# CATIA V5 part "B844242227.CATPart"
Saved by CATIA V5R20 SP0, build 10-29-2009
Part number: B844242227
Revision: 2
Definition: design
Nomenclature: B844242227
Source: made
Description: NOT SPECIFIED
Bounding box of the stored display mesh (mm): x -20.5 to 20.5, y -20.5 to 20.5, z -22 to 27
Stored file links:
  C:\Users\Utente\Desktop\3D files B844\B844242227.CATPart
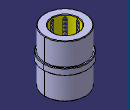
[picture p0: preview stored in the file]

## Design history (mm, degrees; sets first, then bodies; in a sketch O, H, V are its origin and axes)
Body1 "MANIFOLD_SOLID_BREP #38" (main body)
  Solid1: solid without history
Body2 "MANIFOLD_SOLID_BREP #76"
  Solid2: solid without history
Body3 "MANIFOLD_SOLID_BREP #114"
  Solid3: solid without history
Body4 "MANIFOLD_SOLID_BREP #152"
  Solid4: solid without history
Body5 "MANIFOLD_SOLID_BREP #190"
  Solid5: solid without history
Body6 "MANIFOLD_SOLID_BREP #228"
  Solid6: solid without history
Body7 "MANIFOLD_SOLID_BREP #266"
  Solid7: solid without history
Body8 "MANIFOLD_SOLID_BREP #304"
  Solid8: solid without history
Body9 "MANIFOLD_SOLID_BREP #2370"
  Solid9: solid without history
Body10 "MANIFOLD_SOLID_BREP #2408"
  Solid10: solid without history
Body11 "MANIFOLD_SOLID_BREP #2446"
  Solid11: solid without history
Body12 "MANIFOLD_SOLID_BREP #2484"
  Solid12: solid without history
Body13 "MANIFOLD_SOLID_BREP #2522"
  Solid13: solid without history
Body14 "MANIFOLD_SOLID_BREP #2560"
  Solid14: solid without history
Body15 "MANIFOLD_SOLID_BREP #2598"
  Solid15: solid without history
Body16 "MANIFOLD_SOLID_BREP #2636"
  Solid16: solid without history
Body17 "MANIFOLD_SOLID_BREP #2674"
  Solid17: solid without history
Body18 "MANIFOLD_SOLID_BREP #2712"
  Solid18: solid without history
Body19 "MANIFOLD_SOLID_BREP #2750"
  Solid19: solid without history
Body20 "MANIFOLD_SOLID_BREP #2788"
  Solid20: solid without history
Body21 "MANIFOLD_SOLID_BREP #2826"
  Solid21: solid without history
Body22 "MANIFOLD_SOLID_BREP #2864"
  Solid22: solid without history
Body23 "MANIFOLD_SOLID_BREP #2902"
  Solid23: solid without history
Body24 "MANIFOLD_SOLID_BREP #2940"
  Solid24: solid without history
Body25 "MANIFOLD_SOLID_BREP #2978"
  Solid25: solid without history
Body26 "MANIFOLD_SOLID_BREP #3016"
  Solid26: solid without history
Body27 "MANIFOLD_SOLID_BREP #3054"
  Solid27: solid without history
Body28 "MANIFOLD_SOLID_BREP #3092"
  Solid28: solid without history
Body29 "MANIFOLD_SOLID_BREP #3130"
  Solid29: solid without history
Body30 "MANIFOLD_SOLID_BREP #3168"
  Solid30: solid without history
Body31 "MANIFOLD_SOLID_BREP #3206"
  Solid31: solid without history
Body32 "MANIFOLD_SOLID_BREP #3244"
  Solid32: solid without history
Body33 "MANIFOLD_SOLID_BREP #3282"
  Solid33: solid without history
Body34 "MANIFOLD_SOLID_BREP #3320"
  Solid34: solid without history
Body35 "MANIFOLD_SOLID_BREP #3358"
  Solid35: solid without history
Body36 "MANIFOLD_SOLID_BREP #3396"
  Solid36: solid without history
Body37 "MANIFOLD_SOLID_BREP #3434"
  Solid37: solid without history
Body38 "MANIFOLD_SOLID_BREP #3472"
  Solid38: solid without history
Body39 "MANIFOLD_SOLID_BREP #3510"
  Solid39: solid without history
Body40 "MANIFOLD_SOLID_BREP #3548"
  Solid40: solid without history
Body41 "MANIFOLD_SOLID_BREP #3586"
  Solid41: solid without history
Body42 "MANIFOLD_SOLID_BREP #3624"
  Solid42: solid without history
Body43 "MANIFOLD_SOLID_BREP #3662"
  Solid43: solid without history
Body44 "MANIFOLD_SOLID_BREP #3700"
  Solid44: solid without history
Body45 "MANIFOLD_SOLID_BREP #3738"
  Solid45: solid without history
Body46 "MANIFOLD_SOLID_BREP #3776"
  Solid46: solid without history
Body47 "MANIFOLD_SOLID_BREP #3814"
  Solid47: solid without history
Body48 "MANIFOLD_SOLID_BREP #3852"
  Solid48: solid without history
Body49 "MANIFOLD_SOLID_BREP #3890"
  Solid49: solid without history
Body50 "MANIFOLD_SOLID_BREP #3928"
  Solid50: solid without history
Body51 "MANIFOLD_SOLID_BREP #3966"
  Solid51: solid without history
Body52 "MANIFOLD_SOLID_BREP #4004"
  Solid52: solid without history
Body53 "MANIFOLD_SOLID_BREP #4042"
  Solid53: solid without history
Body54 "MANIFOLD_SOLID_BREP #4080"
  Solid54: solid without history
Body55 "MANIFOLD_SOLID_BREP #4118"
  Solid55: solid without history
Body56 "MANIFOLD_SOLID_BREP #4156"
  Solid56: solid without history
Body57 "MANIFOLD_SOLID_BREP #4194"
  Solid57: solid without history
Body58 "MANIFOLD_SOLID_BREP #4232"
  Solid58: solid without history
Body59 "MANIFOLD_SOLID_BREP #4270"
  Solid59: solid without history
Body60 "MANIFOLD_SOLID_BREP #4308"
  Solid60: solid without history
Body61 "MANIFOLD_SOLID_BREP #4346"
  Solid61: solid without history
Body62 "MANIFOLD_SOLID_BREP #4384"
  Solid62: solid without history
Body63 "MANIFOLD_SOLID_BREP #4422"
  Solid63: solid without history
Body64 "MANIFOLD_SOLID_BREP #4460"
  Solid64: solid without history
Body65 "MANIFOLD_SOLID_BREP #4498"
  Solid65: solid without history
Body66 "MANIFOLD_SOLID_BREP #4536"
  Solid66: solid without history
Body67 "MANIFOLD_SOLID_BREP #4574"
  Solid67: solid without history
Body68 "MANIFOLD_SOLID_BREP #4612"
  Solid68: solid without history
Body69 "MANIFOLD_SOLID_BREP #4650"
  Solid69: solid without history
Body70 "MANIFOLD_SOLID_BREP #4688"
  Solid70: solid without history
Body71 "MANIFOLD_SOLID_BREP #4726"
  Solid71: solid without history
Body72 "MANIFOLD_SOLID_BREP #4764"
  Solid72: solid without history
Body73 "MANIFOLD_SOLID_BREP #4802"
  Solid73: solid without history
Body74 "MANIFOLD_SOLID_BREP #4840"
  Solid74: solid without history
Body75 "MANIFOLD_SOLID_BREP #4878"
  Solid75: solid without history
Body76 "MANIFOLD_SOLID_BREP #4916"
  Solid76: solid without history
Body77 "MANIFOLD_SOLID_BREP #4954"
  Solid77: solid without history
Body78 "MANIFOLD_SOLID_BREP #4992"
  Solid78: solid without history
Body79 "MANIFOLD_SOLID_BREP #5030"
  Solid79: solid without history
Body80 "MANIFOLD_SOLID_BREP #5068"
  Solid80: solid without history
Body81 "MANIFOLD_SOLID_BREP #5106"
  Solid81: solid without history
Body82 "MANIFOLD_SOLID_BREP #5144"
  Solid82: solid without history
Body83 "MANIFOLD_SOLID_BREP #5182"
  Solid83: solid without history
Body84 "MANIFOLD_SOLID_BREP #5220"
  Solid84: solid without history
Body85 "MANIFOLD_SOLID_BREP #5258"
  Solid85: solid without history
Body86 "MANIFOLD_SOLID_BREP #5296"
  Solid86: solid without history
Body87 "MANIFOLD_SOLID_BREP #5334"
  Solid87: solid without history
Body88 "MANIFOLD_SOLID_BREP #5372"
  Solid88: solid without history
Body89 "MANIFOLD_SOLID_BREP #5410"
  Solid89: solid without history
Body90 "MANIFOLD_SOLID_BREP #5448"
  Solid90: solid without history
Body91 "MANIFOLD_SOLID_BREP #5486"
  Solid91: solid without history
Body92 "MANIFOLD_SOLID_BREP #5524"
  Solid92: solid without history
Body93 "MANIFOLD_SOLID_BREP #5562"
  Solid93: solid without history
Body94 "MANIFOLD_SOLID_BREP #5600"
  Solid94: solid without history
Body95 "MANIFOLD_SOLID_BREP #5638"
  Solid95: solid without history
Body96 "MANIFOLD_SOLID_BREP #5676"
  Solid96: solid without history
Body97 "MANIFOLD_SOLID_BREP #5714"
  Solid97: solid without history
Body98 "MANIFOLD_SOLID_BREP #5752"
  Solid98: solid without history
Body99 "MANIFOLD_SOLID_BREP #5790"
  Solid99: solid without history
Body100 "MANIFOLD_SOLID_BREP #5828"
  Solid100: solid without history
Body101 "MANIFOLD_SOLID_BREP #5866"
  Solid101: solid without history
Body102 "MANIFOLD_SOLID_BREP #5904"
  Solid102: solid without history
Body103 "MANIFOLD_SOLID_BREP #5942"
  Solid103: solid without history
Body104 "MANIFOLD_SOLID_BREP #5980"
  Solid104: solid without history
Body105 "MANIFOLD_SOLID_BREP #6018"
  Solid105: solid without history
Body106 "MANIFOLD_SOLID_BREP #6056"
  Solid106: solid without history
Body107 "MANIFOLD_SOLID_BREP #6094"
  Solid107: solid without history
Body108 "MANIFOLD_SOLID_BREP #6132"
  Solid108: solid without history
Body109 "MANIFOLD_SOLID_BREP #6170"
  Solid109: solid without history
Body110 "MANIFOLD_SOLID_BREP #6208"
  Solid110: solid without history
Body111 "MANIFOLD_SOLID_BREP #6246"
  Solid111: solid without history
Body112 "MANIFOLD_SOLID_BREP #6284"
  Solid112: solid without history
Body113 "MANIFOLD_SOLID_BREP #6322"
  Solid113: solid without history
